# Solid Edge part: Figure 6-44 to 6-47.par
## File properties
Author: Ashutosh-CADCIM
Template: Iso Metric Part.par
Last saved by: Ashutosh-CADCIM
Revision: 1
Application: Solid Edge
Accuracy: 0.990
Username: Ashutosh-CADCIM
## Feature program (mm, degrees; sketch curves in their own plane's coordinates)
sketch for "unnamed Protrusion 1" plane through (0, 0, 0) normal (0, 0, 1) x-axis (1, 0, 0)
  line (-100, -100) -> (100, -100)
  line (100, -100) -> (100, 100)
  line (100, 100) -> (-100, 100)
  line (-100, 100) -> (-100, -100)
extrude "unnamed Protrusion 1" add finite 20 symmetric
sketch for "ExtrudedCutout_1" plane through (0, 0, 10) normal (0, 0, 1) x-axis (1, 0, 0)
  circle centre (0, 0) radius 7.5
extrude "ExtrudedCutout_1" cut finite 81.8886 along -normal
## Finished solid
Body 1: solid body, 7 faces, 14 edges, 8 vertices.
  Faces by surface: plane 6, cylinder 1
  Edges by curve: line 12, circle 2
Bounding box of the edges (mm): 200.000 x 200.000 x 20.000, from (-100, -100, -10) to (100, 100, 10).
Cylindrical faces by radius (mm): R7.5 x1
Planar faces by outward normal: +x 1, +y 1, +z 1, -x 1, -y 1, -z 1
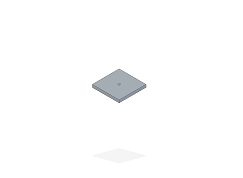
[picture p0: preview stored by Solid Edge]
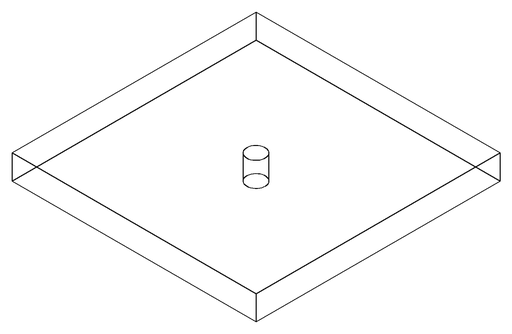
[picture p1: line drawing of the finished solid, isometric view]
